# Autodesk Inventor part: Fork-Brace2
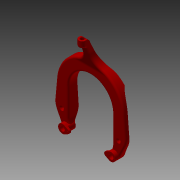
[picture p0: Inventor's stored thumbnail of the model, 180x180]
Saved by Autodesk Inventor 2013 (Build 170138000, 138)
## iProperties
Shininess: 64.0
Length Units: 11272
Angle Units: 11279
Time Units: 11290
Mass Units: 11286
Length Display Precision: 3
Angle Display Precision: 2
Compacted: True
Part Number: Fork-Brace2
Document SubType Name: Modeling
Created: 2003-10
Designer: Autodesk, Inc.
Manufacturer: Standard
Standards Organization: Custom
Mass: 76.1205 g
Surface Area: 223.813 cm^2
Volume: 76.1205 cm^3
Density: 1 g/cm^3
Material: Generic
Density: 0.0
Volumn: 0.0
Area: 0.0
PropertySet Name: Model Information
Control State: 0
Master: False
Checked Out: False
Translation Standard: STEP AP214DIS
File Name: D:\\Documents and Settings\\garding\\My Documents\\My Work\\My Models\\Specialized M4\\Fork\\BRACE.stp
Preprocessor: Autodesk Inventor 8 Pre-Release
Postprocessor: Build: 057b, Release: 8 Pre-Release - Date: Sun 09/16/2003
Sent Units: INCHES
Uncertainty: 1.0000000000000002e-06
Author: Autodesk, Inc.
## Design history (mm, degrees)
feature "Base1"
sketch "Sketch1"
  geometry: L1 (-40.83, 0)-(-40.83, -45.941); L2 (38.288, -53.783)-(39.968, -52.909) reference; L3 (55.902, -40.649)-(48.019, -56.676) reference; L4 (54.945, 5.098)-(58.089, -28.786) reference; L5 (-27.85, 47.638)-(27.85, 47.638) reference; L6 (-58.09, -28.785)-(-54.945, 5.1) reference; L7 (-48.02, -56.678)-(-55.904, -40.648) reference; L8 (-39.968, -52.909)-(-38.288, -53.783) reference; L9 (-40.83, 0)-(-40.83, -45.941) reference; L10 (40.831, -45.941)-(40.831, 0) reference; C1 r 6.35 at (-48.578, -36.14); A1 r 7.302 centre (41.657, -60.261) between (48.019, -56.676) and (38.288, -53.783) reference; A2 r 22.225 centre (35.959, -30.839) between (55.902, -40.649) and (58.184, -30.839) reference; A3 r 22.225 centre (35.959, -30.839) between (58.184, -30.839) and (58.089, -28.786) reference; A4 r 55.181 centre (0, 0) between (54.945, 5.098) and (27.85, 47.638) reference; A5 r 55.182 centre (0, 0) between (-27.85, 47.638) and (-54.945, 5.1) reference; A6 r 22.225 centre (-35.961, -30.839) between (-58.09, -28.785) and (-58.186, -30.839) reference; A7 r 22.225 centre (-35.961, -30.839) between (-58.186, -30.839) and (-55.904, -40.648) reference; A8 r 7.302 centre (-41.657, -60.261) between (-38.288, -53.783) and (-48.02, -56.678) reference; A9 r 28.575 centre (-12.255, -45.941) between (-40.83, -45.941) and (-39.968, -52.909) reference; A10 r 40.83 centre (0, 0) between (40.831, 0) and (-40.83, 0) reference; A11 r 28.575 centre (12.255, -45.941) between (39.968, -52.909) and (40.831, -45.941) reference
  constraints: 2 end point, 1 centre point
  dimensions: "d15" = 7.74707 distance from line of C1.centre L1
hole "Hole1" sketch "Sketch1" at (-48.578, -36.14) diameter "d0" = 3.2512; stored, may be unused: countersink angle "d4" = 90 deg, drill point angle "d6" = 118 deg; dims "d1" = 12.7, "d2" = 7.62, "d3" = 6.35, "d5" = 19.05
workplane "Work Plane1"
sketch "Sketch2"
  geometry: C1 r 3.81 at (-89.044, -0.261) reference
hole "Hole2" sketch "Sketch2" at (-89.044, -0.261) diameter "d7" = 12.7; stored, may be unused: countersink angle "d11" = 0.1 deg, drill point angle "d13" = 0 deg; dims "d8" = 12.7, "d9" = 9.525, "d10" = 6.35, "d12" = 12.7
workaxis "Work Axis1"
workplane "Work Plane2"
mirror "Mirror1"
body "Solid1"
other parameters: "d14" = 0
